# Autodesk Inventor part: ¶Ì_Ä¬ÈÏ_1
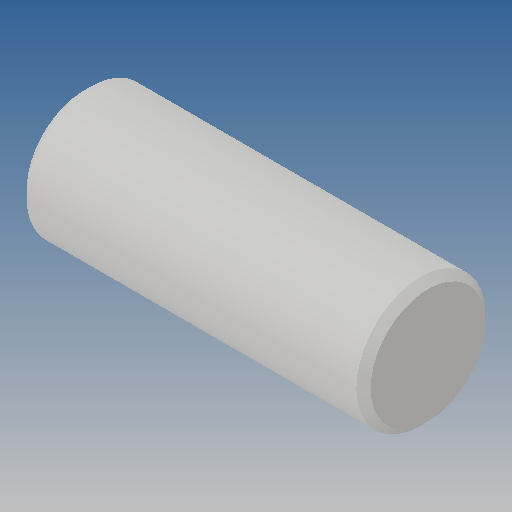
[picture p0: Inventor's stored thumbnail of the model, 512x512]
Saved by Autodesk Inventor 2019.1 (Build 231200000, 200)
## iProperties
Created: 2012-10
Part Number: ¶Ì_Ä¬ÈÏ_1
Material: Ogólny
Document SubType Name: Modeling
Designer: CADENGINEERING4
Density: 1 g/cm^3
Appearance: Domyślna
Author: CADENGINEERING4
Revision Number: ÈÎºÎ
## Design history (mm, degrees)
feature "NONE"
node "Bryła1"
